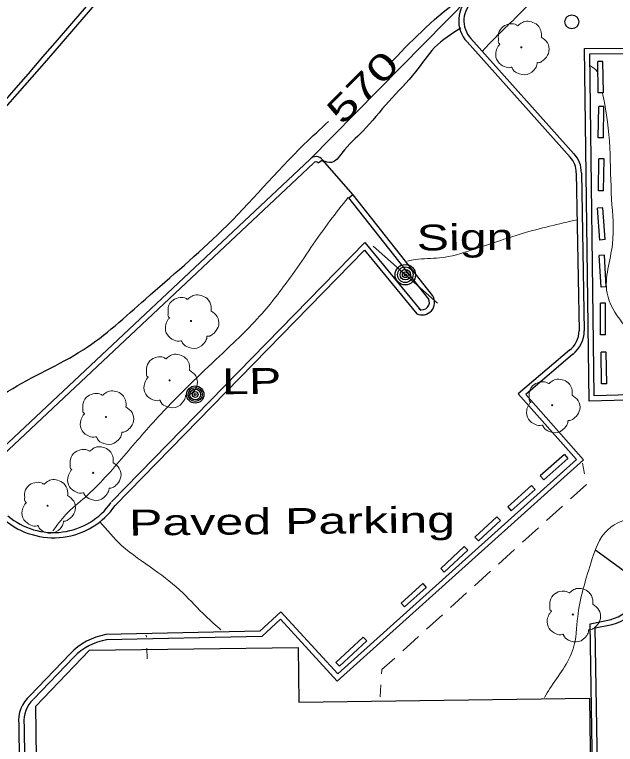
# Model space of a CAD drawing. Extents: x 2361708 to 2370558, y 6977955 to 6991887.
# Drawn here: x 2368794 to 2368905.6, y 6989867.8 to 6990003.4 of the extents above; entities that cross this region are included whole.
import ezdxf
from ezdxf.enums import TextEntityAlignment as Align

# ---------------------------------------------------------------- set-up
doc = ezdxf.new("R2010")
doc.units = 0
doc.header["$LTSCALE"] = 1.9
for name, color, linetype, lineweight in [('11', 7, 'Continuous', 25), ('13', 7, 'Continuous', 13), ('2', 7, 'Continuous', 25), ('20', 7, 'Continuous', 25), ('21', 7, 'Continuous', 25), ('23', 7, 'Continuous', 25), ('29', 7, 'Continuous', 13), ('31', 7, 'Continuous', 13), ('35', 7, 'Continuous', 13)]:
    doc.layers.add(name, color=color, linetype=linetype, lineweight=lineweight)

msp = doc.modelspace()

# ---------------------------------------------------------------- linework, layer by layer
at = {"layer": '11'}
msp.add_line((2368797.95, 6989874.917), (2368807.931, 6989885.303), dxfattribs=at)
msp.add_lwpolyline([(2368807.931, 6989885.303), (2368846.628, 6989885.831), (2368846.765, 6989875.662), (2368900.751, 6989876.386), (2368901.312, 6989834.199), (2368886.614, 6989833.999), (2368886.899, 6989813.441), (2368808.746, 6989812.357), (2368808.414, 6989836.695), (2368798.465, 6989836.56), (2368797.95, 6989874.917)], dxfattribs=at)
at = {"layer": '13'}
for p, q in [((2368899.435, 6989920.045), (2368899.804, 6989918.079)), ((2368895.741, 6989912.07), (2368892.776, 6989909.382)), ((2368891.289, 6989908.037), (2368888.324, 6989905.349)), ((2368886.837, 6989904.005), (2368883.872, 6989901.317)), ((2368882.385, 6989899.972), (2368879.421, 6989897.284)), ((2368877.934, 6989895.94), (2368874.969, 6989893.252)), ((2368873.482, 6989891.907), (2368870.517, 6989889.219)), ((2368818.469, 6989887.713), (2368818.455, 6989888.113)), ((2368869.03, 6989887.875), (2368866.065, 6989885.196)), ((2368818.627, 6989883.715), (2368818.548, 6989885.714)), ((2368862.025, 6989878.908), (2368861.886, 6989876.626))]:
    msp.add_line(p, q, dxfattribs=at)
for points in [[(2368900.163, 6989916.113), (2368900.173, 6989916.082), (2368897.228, 6989913.414)], [(2368864.578, 6989883.852), (2368862.198, 6989881.699), (2368862.146, 6989880.909)]]:
    msp.add_lwpolyline(points, dxfattribs=at)
at = {"layer": '2'}
for p, q in [((2368878.629, 6990006.722), (2368848.826, 6989976.477)), ((2368878.019, 6989998.286), (2368897.154, 6989976.897)), ((2368878.733, 6989998.922), (2368897.867, 6989977.533)), ((2368903.235, 6989994.666), (2368902.275, 6989994.646)), ((2368902.391, 6989988.817), (2368902.275, 6989994.646)), ((2368903.35, 6989988.836), (2368903.235, 6989994.666)), ((2368903.35, 6989988.836), (2368902.391, 6989988.817)), ((2368902.37, 6989980.486), (2368902.464, 6989986.328)), ((2368903.424, 6989986.317), (2368902.464, 6989986.328)), ((2368903.33, 6989980.476), (2368903.424, 6989986.317)), ((2368903.33, 6989980.476), (2368902.37, 6989980.486)), ((2368848.826, 6989976.477), (2368789.325, 6989920.567)), ((2368850.392, 6989975.821), (2368851.156, 6989976.399)), ((2368856.849, 6989969.913), (2368851.156, 6989976.399)), ((2368902.423, 6989970.666), (2368902.497, 6989976.587)), ((2368903.457, 6989976.577), (2368902.497, 6989976.587)), ((2368903.384, 6989970.655), (2368903.457, 6989976.577)), ((2368849.482, 6989975.773), (2368789.982, 6989919.864)), ((2368898.301, 6989973.987), (2368898.811, 6989944.641)), ((2368899.262, 6989974.007), (2368899.771, 6989944.66)), ((2368856.094, 6989969.316), (2368856.798, 6989969.972)), ((2368871.658, 6989951.133), (2368856.849, 6989969.913)), ((2368903.384, 6989970.655), (2368902.423, 6989970.666)), ((2368870.904, 6989950.536), (2368856.094, 6989969.316)), ((2368903.213, 6989967.494), (2368902.254, 6989967.425)), ((2368902.7, 6989961.499), (2368902.254, 6989967.425)), ((2368903.66, 6989961.568), (2368903.213, 6989967.494)), ((2368903.66, 6989961.568), (2368902.7, 6989961.499)), ((2368903.528, 6989958.666), (2368902.568, 6989958.607)), ((2368903.864, 6989952.789), (2368903.528, 6989958.666)), ((2368902.904, 6989952.73), (2368902.568, 6989958.607)), ((2368903.864, 6989952.789), (2368902.904, 6989952.73)), ((2368902.788, 6989943.899), (2368902.772, 6989949.789)), ((2368903.732, 6989949.788), (2368902.772, 6989949.789)), ((2368903.748, 6989943.898), (2368903.732, 6989949.788)), ((2368903.748, 6989943.898), (2368902.788, 6989943.899)), ((2368903.849, 6989940.688), (2368902.889, 6989940.669)), ((2368903.005, 6989934.79), (2368902.889, 6989940.669)), ((2368903.965, 6989934.809), (2368903.849, 6989940.688)), ((2368903.965, 6989934.809), (2368903.005, 6989934.79)), ((2368896.11, 6989921.634), (2368891.617, 6989917.671)), ((2368896.747, 6989920.91), (2368892.254, 6989916.947)), ((2368896.11, 6989921.634), (2368896.747, 6989920.91)), ((2368891.617, 6989917.671), (2368892.254, 6989916.947)), ((2368889.994, 6989915.906), (2368885.582, 6989911.923)), ((2368889.994, 6989915.906), (2368890.641, 6989915.192)), ((2368890.641, 6989915.192), (2368886.229, 6989911.209)), ((2368885.582, 6989911.923), (2368886.229, 6989911.209)), ((2368883.549, 6989910.114), (2368879.485, 6989906.325)), ((2368883.549, 6989910.114), (2368884.205, 6989909.41)), ((2368884.205, 6989909.41), (2368880.141, 6989905.621)), ((2368879.485, 6989906.325), (2368880.141, 6989905.621)), ((2368877.501, 6989904.576), (2368873.12, 6989900.504)), ((2368877.501, 6989904.576), (2368878.158, 6989903.872)), ((2368878.158, 6989903.872), (2368873.776, 6989899.801)), ((2368873.12, 6989900.504), (2368873.776, 6989899.801)), ((2368869.786, 6989897.672), (2368865.781, 6989894.074)), ((2368869.786, 6989897.672), (2368870.423, 6989896.958)), ((2368870.423, 6989896.958), (2368866.417, 6989893.36)), ((2368865.781, 6989894.074), (2368866.417, 6989893.36)), ((2368858.75, 6989887.757), (2368853.675, 6989883.048)), ((2368859.407, 6989887.053), (2368854.331, 6989882.345)), ((2368858.75, 6989887.757), (2368859.407, 6989887.053)), ((2368804.317, 6989884.658), (2368796.841, 6989876.857)), ((2368805.014, 6989883.995), (2368797.538, 6989876.193)), ((2368853.675, 6989883.048), (2368854.331, 6989882.345)), ((2368794.792, 6989871.558), (2368795.448, 6989816.261)), ((2368795.752, 6989871.567), (2368796.408, 6989816.27))]:
    msp.add_line(p, q, dxfattribs=at)
for points in [[(2368921.571, 6989932.137), (2368900.685, 6989931.578), (2368899.822, 6989997.073), (2368925.013, 6989997.123)], [(2368921.542, 6989933.096), (2368901.636, 6989932.567), (2368900.791, 6989996.112), (2368925.012, 6989996.163)], [(2368812.019, 6989912.873), (2368859.063, 6989961.033), (2368869.423, 6989948.411)], [(2368812.706, 6989912.199), (2368858.997, 6989959.593), (2368868.679, 6989947.804)], [(2368897.045, 6989941.014), (2368887.532, 6989932.903), (2368898.318, 6989920.765), (2368853.996, 6989880.911), (2368843.425, 6989892.441), (2368839.529, 6989888.844), (2368810.974, 6989888.202)], [(2368897.672, 6989940.28), (2368888.903, 6989932.806), (2368899.669, 6989920.688), (2368853.928, 6989879.56), (2368843.368, 6989891.08), (2368839.918, 6989887.888), (2368810.993, 6989887.242)], [(2368902.13, 6989812.396), (2368900.859, 6989890.237), (2368904.802, 6989891.045)], [(2368885.755, 6989694.114), (2368907.479, 6989693.801), (2368906.437, 6989768.554), (2368908.606, 6989768.745), (2368908.541, 6989771.375), (2368903.761, 6989771.3), (2368901.836, 6989889.457), (2368904.99, 6989890.107)]]:
    msp.add_lwpolyline(points, dxfattribs=at)
for centre, radius, start, end in [((2367011.023, 6991843.143), 2522.318, 310.35959, 318.61277), ((2367673.36, 6990971.677), 1490.166, 312.88866, 323.04033), ((2367673.36, 6990971.677), 1491.126, 312.88866, 323.04033), ((2368882.222, 6990002.222), 5.758, 128.61026, 223.12325), ((2368882.222, 6990002.222), 4.798, 128.61026, 223.12325), ((2368849.961, 6989975.506), 1.492, 36.73631, 139.48971), ((2368894.011, 6989973.976), 4.29, 0.15151, 42.8995), ((2368894.011, 6989973.976), 5.25, 0.15151, 42.8995), ((2368849.961, 6989975.506), 0.532, 36.73631, 139.48971), ((2368869.666, 6989949.919), 2.333, 244.98814, 31.35951), ((2368869.666, 6989949.919), 1.373, 244.98814, 31.35951), ((2368894.223, 6989944.631), 4.588, 307.96206, 0.11646), ((2368894.223, 6989944.631), 5.548, 307.96206, 0.11646), ((2368801.211, 6989920.215), 13.053, 229.66168, 325.11021), ((2368801.211, 6989920.215), 14.014, 229.66168, 325.11021), ((2368902.193, 6989899.781), 9.11, 286.12973, 357.41576), ((2368902.193, 6989899.781), 10.07, 286.12973, 357.41576), ((2368812.986, 6989876.398), 11.974, 99.67427, 136.38135), ((2368812.986, 6989876.398), 11.014, 99.67427, 136.38135), ((2368800.907, 6989872.239), 6.153, 131.36712, 186.36586), ((2368800.907, 6989872.239), 5.193, 131.36712, 186.36586)]:
    msp.add_arc(centre, radius, start, end, dxfattribs=at)
at = {"layer": '20'}
for radius in [1.6, 1.3, 1, 0.539, 0.192]:
    msp.add_circle((2368827.55, 6989932.802), radius, dxfattribs=at)
at = {"layer": '21'}
for p, q in [((2368872.541, 6989949.771), (2368860.559, 6989960.338)), ((2368913.672, 6989895.22), (2368901.909, 6989903.848))]:
    msp.add_line(p, q, dxfattribs=at)
for radius in [1.9, 1.442, 0.973, 0.539, 0.192]:
    msp.add_circle((2368866.55, 6989955.054), radius, dxfattribs=at)
at = {"layer": '23'}
msp.add_circle((2368897.475, 6990002.021), 1.3, dxfattribs=at)
at = {"layer": '29'}
for centre in [(2368888.089, 6989997.291), (2368826.76, 6989946.465), (2368822.775, 6989935.437), (2368893.822, 6989930.813), (2368810.959, 6989928.644), (2368808.598, 6989918.251), (2368800.135, 6989912.14), (2368897.652, 6989891.947)]:
    msp.add_circle(centre, 0.1, dxfattribs=at)
for points in [[(2368884.123, 6989997.864), (2368884.143, 6989997.874), (2368884.062, 6989997.943), (2368883.826, 6989998.571), (2368883.865, 6989999.851), (2368884.753, 6990001.15), (2368886.058, 6990001.632), (2368887.18, 6990001.443), (2368887.411, 6990001.315), (2368887.481, 6990001.316), (2368887.531, 6990001.356), (2368887.878, 6990001.649), (2368888.743, 6990002.098), (2368889.954, 6990002.029), (2368891.07, 6990001.44), (2368891.804, 6990000.017), (2368891.812, 6989999.157)], [(2368891.802, 6989999.177), (2368892.942, 6989998.118), (2368893.227, 6989996.53), (2368892.519, 6989995.204), (2368891.865, 6989994.657), (2368891.196, 6989994.441), (2368891.046, 6989994.429), (2368891.028, 6989994.319), (2368890.706, 6989993.416), (2368889.167, 6989992.251), (2368887.275, 6989992.533), (2368886.375, 6989993.475), (2368886.305, 6989993.604), (2368886.184, 6989993.583), (2368884.973, 6989993.702), (2368883.704, 6989994.699), (2368883.358, 6989996.336), (2368883.728, 6989997.36), (2368884.054, 6989997.803), (2368884.123, 6989997.854)], [(2368822.794, 6989947.037), (2368822.814, 6989947.048), (2368822.734, 6989947.117), (2368822.498, 6989947.744), (2368822.536, 6989949.025), (2368823.423, 6989950.323), (2368824.729, 6989950.806), (2368825.85, 6989950.617), (2368826.082, 6989950.489), (2368826.151, 6989950.489), (2368826.201, 6989950.53), (2368826.549, 6989950.823), (2368827.415, 6989951.272), (2368828.625, 6989951.203), (2368829.741, 6989950.614), (2368830.474, 6989949.191), (2368830.482, 6989948.331)], [(2368830.472, 6989948.35), (2368831.612, 6989947.291), (2368831.897, 6989945.704), (2368831.19, 6989944.377), (2368830.535, 6989943.831), (2368829.867, 6989943.614), (2368829.717, 6989943.603), (2368829.699, 6989943.493), (2368829.377, 6989942.59), (2368827.838, 6989941.425), (2368825.945, 6989941.707), (2368825.046, 6989942.649), (2368824.975, 6989942.778), (2368824.855, 6989942.757), (2368823.644, 6989942.876), (2368822.375, 6989943.873), (2368822.029, 6989945.51), (2368822.399, 6989946.533), (2368822.725, 6989946.977), (2368822.794, 6989947.028)], [(2368818.809, 6989936.009), (2368818.829, 6989936.019), (2368818.748, 6989936.089), (2368818.512, 6989936.716), (2368818.55, 6989937.996), (2368819.438, 6989939.295), (2368820.744, 6989939.778), (2368821.865, 6989939.588), (2368822.097, 6989939.46), (2368822.167, 6989939.461), (2368822.216, 6989939.502), (2368822.563, 6989939.795), (2368823.429, 6989940.243), (2368824.64, 6989940.175), (2368825.755, 6989939.585), (2368826.489, 6989938.162), (2368826.498, 6989937.302)], [(2368826.487, 6989937.322), (2368827.627, 6989936.263), (2368827.912, 6989934.675), (2368827.205, 6989933.349), (2368826.55, 6989932.802), (2368825.882, 6989932.586), (2368825.732, 6989932.575), (2368825.713, 6989932.464), (2368825.392, 6989931.561), (2368823.853, 6989930.397), (2368821.96, 6989930.679), (2368821.061, 6989931.62), (2368820.99, 6989931.749), (2368820.87, 6989931.728), (2368819.659, 6989931.847), (2368818.389, 6989932.845), (2368818.043, 6989934.481), (2368818.414, 6989935.505), (2368818.74, 6989935.948), (2368818.809, 6989935.999)], [(2368889.857, 6989931.385), (2368889.876, 6989931.395), (2368889.796, 6989931.464), (2368889.56, 6989932.092), (2368889.597, 6989933.373), (2368890.485, 6989934.671), (2368891.791, 6989935.154), (2368892.913, 6989934.964), (2368893.144, 6989934.836), (2368893.214, 6989934.837), (2368893.263, 6989934.877), (2368893.611, 6989935.171), (2368894.477, 6989935.619), (2368895.687, 6989935.551), (2368896.803, 6989934.961), (2368897.536, 6989933.538), (2368897.545, 6989932.678)], [(2368806.993, 6989929.216), (2368807.013, 6989929.226), (2368806.933, 6989929.296), (2368806.697, 6989929.923), (2368806.734, 6989931.204), (2368807.622, 6989932.502), (2368808.928, 6989932.985), (2368810.049, 6989932.795), (2368810.28, 6989932.668), (2368810.351, 6989932.668), (2368810.4, 6989932.709), (2368810.747, 6989933.002), (2368811.613, 6989933.45), (2368812.824, 6989933.382), (2368813.94, 6989932.792), (2368814.673, 6989931.369), (2368814.681, 6989930.509)], [(2368897.534, 6989932.698), (2368898.675, 6989931.639), (2368898.96, 6989930.051), (2368898.252, 6989928.725), (2368897.597, 6989928.178), (2368896.929, 6989927.962), (2368896.78, 6989927.95), (2368896.761, 6989927.841), (2368896.439, 6989926.937), (2368894.9, 6989925.772), (2368893.008, 6989926.055), (2368892.109, 6989926.996), (2368892.037, 6989927.126), (2368891.918, 6989927.104), (2368890.706, 6989927.223), (2368889.437, 6989928.221), (2368889.091, 6989929.858), (2368889.461, 6989930.881), (2368889.787, 6989931.324), (2368889.857, 6989931.375)], [(2368814.671, 6989930.53), (2368815.812, 6989929.47), (2368816.097, 6989927.883), (2368815.389, 6989926.556), (2368814.734, 6989926.01), (2368814.066, 6989925.793), (2368813.916, 6989925.782), (2368813.897, 6989925.672), (2368813.576, 6989924.768), (2368812.037, 6989923.604), (2368810.144, 6989923.886), (2368809.245, 6989924.827), (2368809.174, 6989924.956), (2368809.054, 6989924.935), (2368807.843, 6989925.054), (2368806.573, 6989926.052), (2368806.228, 6989927.689), (2368806.598, 6989928.712), (2368806.924, 6989929.155), (2368806.993, 6989929.206)], [(2368804.632, 6989918.823), (2368804.652, 6989918.833), (2368804.571, 6989918.903), (2368804.335, 6989919.53), (2368804.373, 6989920.81), (2368805.261, 6989922.109), (2368806.566, 6989922.592), (2368807.688, 6989922.403), (2368807.919, 6989922.275), (2368807.989, 6989922.276), (2368808.039, 6989922.316), (2368808.386, 6989922.609), (2368809.252, 6989923.057), (2368810.463, 6989922.989), (2368811.578, 6989922.4), (2368812.312, 6989920.976), (2368812.32, 6989920.116)], [(2368812.31, 6989920.136), (2368813.45, 6989919.077), (2368813.735, 6989917.49), (2368813.028, 6989916.163), (2368812.373, 6989915.617), (2368811.705, 6989915.4), (2368811.555, 6989915.389), (2368811.536, 6989915.279), (2368811.215, 6989914.376), (2368809.676, 6989913.211), (2368807.783, 6989913.492), (2368806.884, 6989914.434), (2368806.813, 6989914.564), (2368806.693, 6989914.543), (2368805.482, 6989914.661), (2368804.212, 6989915.659), (2368803.866, 6989917.296), (2368804.237, 6989918.319), (2368804.563, 6989918.762), (2368804.632, 6989918.813)], [(2368796.17, 6989912.712), (2368796.19, 6989912.722), (2368796.109, 6989912.792), (2368795.873, 6989913.419), (2368795.911, 6989914.7), (2368796.798, 6989915.998), (2368798.104, 6989916.481), (2368799.226, 6989916.292), (2368799.457, 6989916.164), (2368799.527, 6989916.164), (2368799.577, 6989916.205), (2368799.924, 6989916.498), (2368800.79, 6989916.947), (2368802.001, 6989916.878), (2368803.116, 6989916.288), (2368803.85, 6989914.865), (2368803.857, 6989914.006)], [(2368803.848, 6989914.026), (2368804.988, 6989912.966), (2368805.273, 6989911.379), (2368804.565, 6989910.052), (2368803.911, 6989909.506), (2368803.243, 6989909.289), (2368803.093, 6989909.278), (2368803.074, 6989909.168), (2368802.753, 6989908.265), (2368801.213, 6989907.1), (2368799.321, 6989907.382), (2368798.422, 6989908.324), (2368798.351, 6989908.453), (2368798.231, 6989908.432), (2368797.02, 6989908.55), (2368795.75, 6989909.548), (2368795.404, 6989911.185), (2368795.775, 6989912.208), (2368796.1, 6989912.651), (2368796.17, 6989912.702)], [(2368893.687, 6989892.52), (2368893.707, 6989892.53), (2368893.626, 6989892.599), (2368893.39, 6989893.227), (2368893.428, 6989894.507), (2368894.316, 6989895.805), (2368895.621, 6989896.288), (2368896.743, 6989896.099), (2368896.974, 6989895.971), (2368897.044, 6989895.972), (2368897.094, 6989896.012), (2368897.441, 6989896.305), (2368898.306, 6989896.754), (2368899.517, 6989896.685), (2368900.633, 6989896.096), (2368901.367, 6989894.673), (2368901.375, 6989893.813)], [(2368901.365, 6989893.833), (2368902.505, 6989892.774), (2368902.79, 6989891.186), (2368902.083, 6989889.859), (2368901.428, 6989889.313), (2368900.76, 6989889.097), (2368900.61, 6989889.085), (2368900.591, 6989888.975), (2368900.269, 6989888.072), (2368898.73, 6989886.907), (2368896.838, 6989887.189), (2368895.939, 6989888.131), (2368895.867, 6989888.26), (2368895.748, 6989888.239), (2368894.536, 6989888.357), (2368893.267, 6989889.355), (2368892.921, 6989890.992), (2368893.292, 6989892.016), (2368893.617, 6989892.459), (2368893.687, 6989892.51)]]:
    msp.add_spline(points, degree=3, dxfattribs=at)
at = {"layer": '31', "lineweight": 25}
for points in [[(2368864.357, 6990139.213), (2368870.081, 6990143.077), (2368874.168, 6990142.306), (2368874.083, 6990139.725), (2368870.013, 6990134.446), (2368859.504, 6990122.765), (2368846.159, 6990107.478), (2368830.2, 6990088.315), (2368808.518, 6990064.237), (2368785.282, 6990038.485), (2368766.959, 6990016.719), (2368750.407, 6989997.911), (2368747.793, 6989995.166)], [(2368863.558, 6989994.118), (2368876.148, 6990005.748), (2368880.024, 6990008.285)], [(2368876.884, 6990000.875), (2368871.989, 6989997.238), (2368868.422, 6989992.724), (2368863.484, 6989987.227), (2368858.705, 6989981.791), (2368854.774, 6989977.653), (2368852.851, 6989975.915), (2368851.249, 6989976.17), (2368851.078, 6989976.208)], [(2368698.811, 6989870.043), (2368712.238, 6989877.832), (2368724.952, 6989884.773), (2368739.598, 6989895.843), (2368755.316, 6989906.633), (2368774.542, 6989918.677), (2368792.812, 6989933.431), (2368806.72, 6989941.104), (2368818.291, 6989950.515), (2368832.56, 6989963.321), (2368847.789, 6989979.277), (2368852.318, 6989983.54)]]:
    msp.add_spline(points, degree=3, dxfattribs=at)
at = {"layer": '35'}
for points in [[(2369047.828, 6990605.451), (2369038.394, 6990593.231), (2369027.418, 6990575.906), (2369015.841, 6990558.825), (2369000.65, 6990535.639), (2368993.146, 6990516.056), (2368986.096, 6990501.379), (2368978.606, 6990487.716), (2368969.405, 6990472.988), (2368958.108, 6990456.92), (2368955.454, 6990452.025), (2368953.073, 6990437.411), (2368952.752, 6990420.737), (2368959.614, 6990409.992), (2368963.269, 6990401.087), (2368969.023, 6990386.05), (2368979.207, 6990379.327), (2368988.134, 6990377.652), (2368992.144, 6990375.52), (2368991.785, 6990372.277), (2368987.467, 6990362.585), (2368986.816, 6990353.218), (2368988.815, 6990341.807), (2368989.62, 6990331.804), (2368986.922, 6990311.667), (2368979.307, 6990292.194), (2368965.455, 6990270.221), (2368943.017, 6990245.776), (2368913.099, 6990212.86), (2368880.694, 6990176.38), (2368844.682, 6990139.715), (2368811.712, 6990113.21), (2368778.447, 6990087.292), (2368739.578, 6990051.33), (2368711.829, 6990035.275), (2368686.864, 6990022.057), (2368673.109, 6990014.046), (2368669.745, 6990012.454), (2368668.706, 6990013.324), (2368669.63, 6990016.033), (2368674.153, 6990022.016), (2368684.646, 6990033.407), (2368697.173, 6990050.577), (2368697.763, 6990054.743), (2368695.615, 6990054.522), (2368688.933, 6990050.498), (2368671.541, 6990036.962), (2368648.494, 6990028.152), (2368625.507, 6990018.213), (2368603.069, 6990007.409), (2368581.573, 6989999.594), (2368572.511, 6989995.447), (2368567.234, 6989993.027)], [(2368665.419, 6989900.607), (2368677.373, 6989911.762), (2368693.287, 6989927.174), (2368712.993, 6989946.642), (2368732.835, 6989967.572), (2368758.018, 6989994.643), (2368775.846, 6990015.994), (2368794.466, 6990034.992), (2368816.414, 6990060.462), (2368831.216, 6990077.154), (2368847.595, 6990096.231), (2368867.322, 6990118.799), (2368888.147, 6990142.489), (2368906.082, 6990162.07), (2368923.733, 6990181.959), (2368941.017, 6990199.525), (2368946.819, 6990204.52), (2368952.901, 6990210.759), (2368956.691, 6990214.905)], [(2368668.649, 6989897.418), (2368678.409, 6989906.921), (2368694.979, 6989923.82), (2368712.296, 6989940.035), (2368727.36, 6989955.469), (2368740.34, 6989969.203), (2368757.154, 6989986.705), (2368776.017, 6990005.415), (2368794.266, 6990025.57), (2368813.337, 6990046.492), (2368829.252, 6990063.944), (2368844.765, 6990081.583), (2368856.025, 6990093.231), (2368868.863, 6990107.104), (2368884.229, 6990124.401), (2368899.88, 6990142.251), (2368909.878, 6990150.886), (2368913.659, 6990149.842), (2368915.826, 6990150.133), (2368916.694, 6990150.351)], [(2368671.224, 6989894.852), (2368682.177, 6989904.037), (2368693.42, 6989915.295), (2368713.27, 6989935.405), (2368736.947, 6989957.881), (2368760.296, 6989982.254), (2368774.164, 6989996.187), (2368784.181, 6990007.113), (2368797.555, 6990021.451), (2368810, 6990034.61), (2368821.79, 6990048.323), (2368838.548, 6990066.483), (2368850.608, 6990078.118), (2368860.353, 6990088.142), (2368867.254, 6990092.287), (2368870.608, 6990091.94), (2368872.307, 6990092.006), (2368876.785, 6990094.298), (2368878.205, 6990095.332)], [(2368965.542, 6990085.613), (2368963.678, 6990086.035), (2368957.113, 6990084.402), (2368953.391, 6990080.387), (2368944.743, 6990070.714), (2368936.305, 6990058.953), (2368925.458, 6990046.97), (2368916.398, 6990039.613), (2368904.465, 6990028.279), (2368895.465, 6990018.783), (2368892.127, 6990009.101), (2368886.909, 6990002.64), (2368884.114, 6989999.954), (2368880.796, 6989996.482)], [(2368610.073, 6989951.353), (2368626.538, 6989962.47), (2368647.173, 6989975.727), (2368678.058, 6989992.182), (2368709.835, 6990008.345), (2368735.247, 6990023.038), (2368759.106, 6990038.966), (2368775.98, 6990051.237), (2368793.264, 6990063.552), (2368798.514, 6990061.492), (2368795.569, 6990056.713), (2368775.311, 6990034.34), (2368753.052, 6990009.916), (2368730.449, 6989984.96), (2368711.765, 6989964.291), (2368695.72, 6989946.798), (2368679.176, 6989930.38), (2368669.498, 6989918.547), (2368664.342, 6989911.767), (2368659.192, 6989906.518)], [(2368919.032, 6990007.686), (2368924.947, 6990012.423), (2368932.938, 6990020.719), (2368945.405, 6990030.588), (2368954.222, 6990030.953), (2368959.021, 6990031.058), (2368962.786, 6990028.444), (2368960.84, 6990021.715), (2368956.386, 6990010.612), (2368949.693, 6989998.308), (2368945.427, 6989988.407), (2368941.542, 6989976.259), (2368943.388, 6989964.076), (2368945.896, 6989954.86), (2368943.856, 6989944.38), (2368939.391, 6989939.557), (2368932.517, 6989936.831), (2368923.771, 6989935.328), (2368917.852, 6989937.272), (2368911.492, 6989941.381), (2368906.847, 6989946.137), (2368904.015, 6989951.631), (2368905.018, 6989960.721), (2368904.858, 6989969.099), (2368904.517, 6989978.657), (2368903.266, 6989988.246), (2368903.141, 6989988.814)], [(2368902.337, 6989992.316), (2368902.317, 6989992.406), (2368900.933, 6989993.834)], [(2368855.913, 6989969.394), (2368852.554, 6989965.051), (2368845.579, 6989955.095), (2368839.967, 6989947.871), (2368832.072, 6989939.955), (2368821.105, 6989929.111), (2368814.288, 6989921.365), (2368807.15, 6989913.767), (2368803.541, 6989910.522), (2368801.13, 6989907.49)], [(2368898.484, 6989965.279), (2368888.248, 6989962.701), (2368879.157, 6989959.724), (2368872.931, 6989958.185), (2368868.453, 6989957.883), (2368866.956, 6989957.588)], [(2368939.948, 6989911.551), (2368939.488, 6989911.516), (2368927.859, 6989910.386), (2368918.549, 6989910.317), (2368909.801, 6989910.084), (2368904.153, 6989907.7), (2368901.002, 6989901.47), (2368898.566, 6989891.506), (2368897.733, 6989885.588), (2368893.403, 6989878.206), (2368892.379, 6989876.546)], [(2368809.854, 6989909.172), (2368813.866, 6989904.79), (2368819.93, 6989900.248), (2368825.241, 6989895.938), (2368829.492, 6989891.648), (2368832.327, 6989889.075)]]:
    msp.add_spline(points, degree=3, dxfattribs=at)

# ---------------------------------------------------------------- texts
at = {"layer": '2', "width": 1.45}
msp.add_text('Paved Parking', height=4.8, rotation=0.545, dxfattribs=at).set_placement((2368815.269, 6989906.604))
at = {"layer": '20', "width": 1.4}
for s, p in [('Sign', (2368868.688, 6989959.535)), ('  LP', (2368827.55, 6989932.802))]:
    msp.add_text(s, height=4.8, rotation=0.545, dxfattribs=at).set_placement(p)
at = {"layer": '31', "width": 1.45}
msp.add_text(' 570 ', height=4.8, rotation=45.545, dxfattribs=at).set_placement((2368860.329, 6989988.202), align=Align.CENTER)

doc.saveas('drawing.dxf')
